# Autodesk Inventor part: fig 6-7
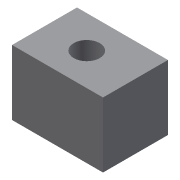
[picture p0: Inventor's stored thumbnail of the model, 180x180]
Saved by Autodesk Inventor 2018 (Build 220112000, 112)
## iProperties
Created: 2009-09
Part Number: fig 6-7
Document SubType Name: Modeling
Designer: Sham
Density: 1 g/cm^3
Material: Generic
Appearance: Default
Author: Sham
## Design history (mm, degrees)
sketch "Sketch1"
  geometry: L1 (-28, 20)-(0, 20); L2 (0, 20)-(0, 0); L3 (0, 0)-(-28, 0); L4 (-28, 0)-(-28, 20)
  constraints: 8 end point, 2 parallel, 1 horizontal, 1 perpendicular
extrude "Extrusion1" new body sketch "Sketch1" distance "d0" = 20; taper "d1" = 0 deg
hole "Hole1" diameter "d4" = 8; stored, may be unused: countersink angle "d8" = 90 deg, drill point angle "d10" = 118 deg; dims "d2" = 10, "d3" = 15, "d5" = 6, "d6" = 4, "d7" = 2, "d9" = 15
body "Solid1"
